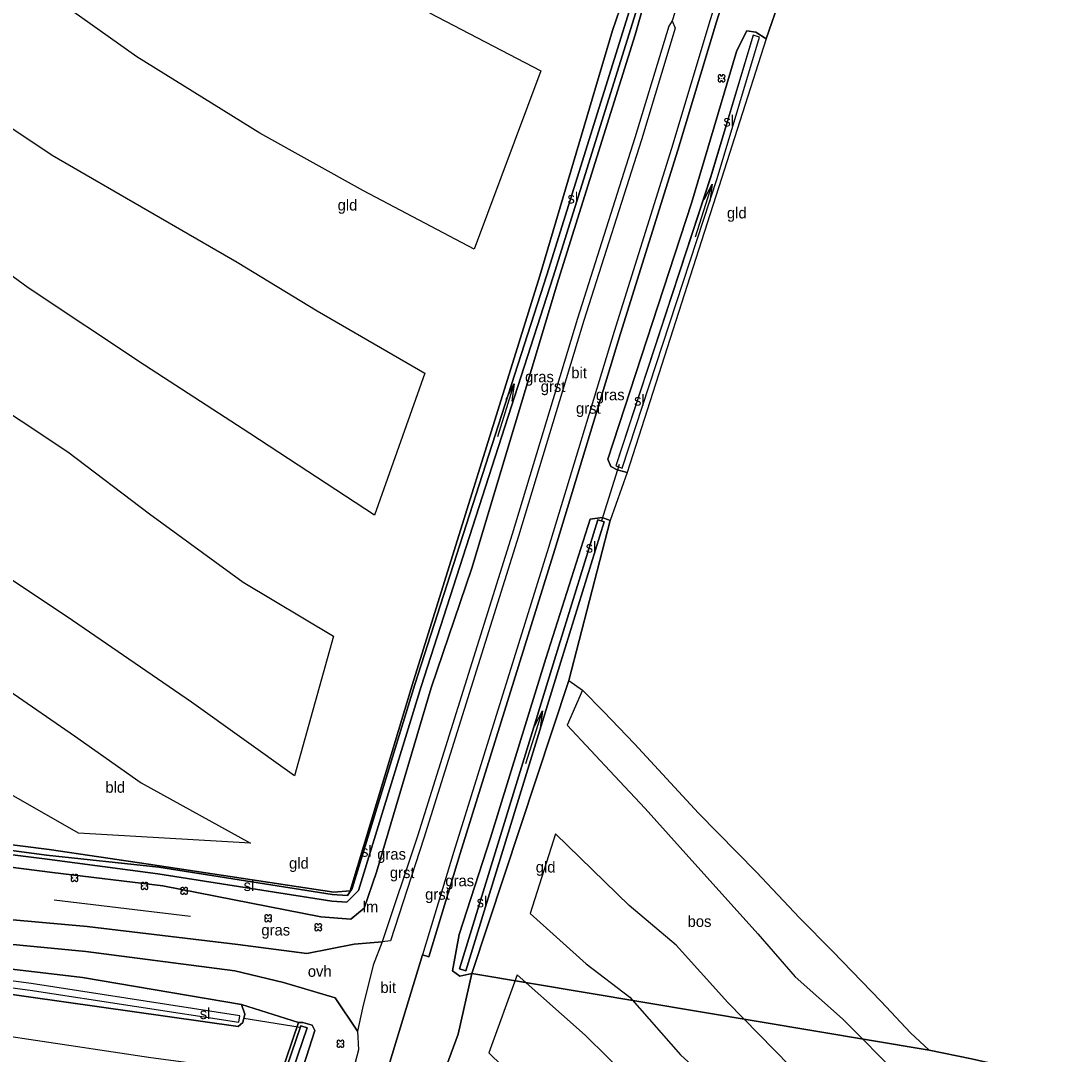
# Model space of a CAD drawing. Extents: x 154825 to 158680, y 370717 to 378075.
# Drawn here: x 155897.3 to 155990.5, y 376817.5 to 376911 of the extents above; entities that cross this region are included whole.
import ezdxf

# ---------------------------------------------------------------- set-up
doc = ezdxf.new("R2010")
doc.units = 0
for name, color, linetype in [('bitumenverharding(vs)', 7, 'Continuous'), ('boom', 7, 'Continuous'), ('bos(vs)', 7, 'Continuous'), ('bouwland_akkerland(vs)', 7, 'Continuous'), ('cultuurscheiding', 7, 'Continuous'), ('duiker lijn', 7, 'Continuous'), ('grasland_productiegrasl(vs)', 7, 'Continuous'), ('grazige vegetatie(vs)', 7, 'Continuous'), ('groensteenverh(vs)', 7, 'Continuous'), ('hoogteverschillijn', 7, 'Continuous'), ('insteek sloot', 7, 'Continuous'), ('maaiveldlijn algemeen', 7, 'Continuous'), ('maaiveldlijn algemeen - gesloten verharding', 7, 'Continuous'), ('maaiveldlijn algemeen - onverhard', 7, 'Continuous'), ('onverhard(vs)', 7, 'Continuous'), ('Sloot bodem', 7, 'Continuous'), ('sloot(vs)', 7, 'Continuous'), ('stroomrichting  watergangen', 7, 'Continuous'), ('verlichtingsobject', 7, 'Continuous'), ('vlak_akkerland', 7, 'Continuous'), ('vlak_Bos', 7, 'Continuous'), ('vlak_Grasland', 7, 'Continuous'), ('vlak_Grazige_vegetatie', 7, 'Continuous')]:
    doc.layers.add(name, color=color, linetype=linetype)

msp = doc.modelspace()

# ---------------------------------------------------------------- linework, layer by layer
at = {"layer": 'boom'}
for centre in [(155960.688, 376905.781), (155902.151, 376833.437), (155908.483, 376832.716), (155912.066, 376832.272), (155919.669, 376829.786), (155924.198, 376828.969), (155926.209, 376818.435)]:
    msp.add_circle(centre, 0.006, dxfattribs=at)
for centre, start, end in [((155960.529, 376905.939), 357.07502, 272.92498), ((155960.846, 376905.939), 267.07502, 182.92498), ((155960.529, 376905.623), 87.07502, 2.92498), ((155960.846, 376905.623), 177.07502, 92.92498), ((155901.993, 376833.595), 357.07502, 272.92498), ((155901.993, 376833.279), 87.07502, 2.92498), ((155902.309, 376833.595), 267.07502, 182.92498), ((155902.309, 376833.279), 177.07502, 92.92498), ((155908.325, 376832.874), 357.07502, 272.92498), ((155908.325, 376832.558), 87.07502, 2.92498), ((155908.641, 376832.874), 267.07502, 182.92498), ((155908.641, 376832.558), 177.07502, 92.92498), ((155911.908, 376832.43), 357.07502, 272.92498), ((155911.908, 376832.114), 87.07502, 2.92498), ((155912.224, 376832.43), 267.07502, 182.92498), ((155912.224, 376832.114), 177.07502, 92.92498), ((155919.511, 376829.945), 357.07502, 272.92498), ((155919.511, 376829.628), 87.07502, 2.92498), ((155919.827, 376829.945), 267.07502, 182.92498), ((155919.827, 376829.628), 177.07502, 92.92498), ((155924.04, 376829.127), 357.07502, 272.92498), ((155924.04, 376828.811), 87.07502, 2.92498), ((155924.356, 376829.127), 267.07502, 182.92498), ((155924.356, 376828.811), 177.07502, 92.92498), ((155926.051, 376818.593), 357.07502, 272.92498), ((155926.051, 376818.277), 87.07502, 2.92498), ((155926.367, 376818.593), 267.07502, 182.92498), ((155926.367, 376818.277), 177.07502, 92.92498)]:
    msp.add_arc(centre, 0.158, start, end, dxfattribs=at)
at = {"layer": 'cultuurscheiding'}
msp.add_lwpolyline([(155979.48, 376817.84), (155938.088, 376824.783)], dxfattribs=at)
at = {"layer": 'duiker lijn'}
for points in [[(155951.437, 376870.843), (155949.812, 376865.757)], [(155922.58, 376819.892), (155917.474, 376820.734)]]:
    msp.add_lwpolyline(points, dxfattribs=at)
at = {"layer": 'groensteenverh(vs)'}
for points in [[(155977.72, 376967.095), (155968.744, 376938.018), (155960.234, 376910.907), (155956.721, 376899.271), (155951.551, 376882.687), (155945.605, 376863.158), (155937.043, 376835.644), (155934.215, 376826.303), (155933.641, 376826.476)], [(155956.222, 376910.974), (155955.911, 376910.5), (155952.857, 376900.403), (155947.662, 376884.051), (155941.732, 376864.545), (155933.195, 376837.219), (155929.981, 376827.647)]]:
    msp.add_lwpolyline(points, dxfattribs=at)
at = {"layer": 'hoogteverschillijn'}
for points in [[(155874.66, 376916.61), (155883.38, 376909.98), (155892.9, 376903.67), (155900.14, 376898.84), (155908.78, 376893.81), (155916.88, 376889.16), (155924.11, 376884.74), (155933.83, 376879.1), (155929.3, 376866.27), (155918.02, 376873.64), (155908.49, 376879.84), (155897.95, 376886.83), (155887.87, 376894.23), (155879.15, 376901.66), (155869.11, 376909.47), (155861.42, 376914.58)], [(155934.27, 376911.71), (155944.34, 376906.47), (155938.31, 376890.31), (155928.29, 376895.61), (155918.93, 376900.81), (155907.78, 376907.73), (155899.49, 376913.63)], [(155893.08, 376877.6), (155901.55, 376871.98), (155908.94, 376866.37), (155917.4, 376860.19), (155925.57, 376855.3), (155922.04, 376842.67), (155912.73, 376849.34), (155901.98, 376856.72), (155891.51, 376863.7)], [(155896.2, 376850.4), (155902.14, 376846.3), (155908.19, 376842.04), (155918.07, 376836.57), (155902.52, 376837.48), (155889.68, 376844.82)], [(155991.54, 376815.37), (155987.15, 376816.19), (155983.3, 376817.06), (155979.48, 376817.84), (155977.78, 376819.42), (155975.13, 376822.26), (155970.74, 376826.8), (155967.74, 376829.82), (155963.85, 376833.97), (155958.6, 376839.3), (155952.8, 376845.56), (155950.02, 376848.51), (155948.11, 376850.44), (155946.71, 376847.26), (155951.01, 376842.68), (155953.78, 376839.71), (155956.93, 376836.2), (155963.97, 376828.38), (155967.35, 376824.5), (155971.64, 376820.68), (155976.86, 376815.44), (155982.97, 376813.8), (155989.69, 376811.89), (155993.57, 376808.55)], [(155994.4, 376800.74), (155989.65, 376805.26), (155985.81, 376808.54), (155979.65, 376810.44), (155973.59, 376812.11), (155966.88, 376816.43), (155961.26, 376822.16), (155956.57, 376827.35), (155952.32, 376830.93), (155945.66, 376837.42), (155943.37, 376830.22), (155948.43, 376825.65), (155952.39, 376822.65), (155956.98, 376817.44), (155961.53, 376813.27), (155966.61, 376809.39), (155973.68, 376806.3), (155978.62, 376805.16), (155983.98, 376802.87), (155990.83, 376797.67)], [(155993.54, 376788.54), (155987.44, 376794.17), (155981.92, 376798.48), (155974.82, 376800.89), (155968.62, 376803.98), (155960.44, 376808.18), (155954.42, 376813.24), (155948.36, 376819.22), (155942.2, 376824.67), (155939.62, 376817.62), (155945.74, 376811.67), (155952.61, 376806.55), (155957.57, 376802.23), (155965.26, 376798.55), (155971.4, 376796.09), (155977.96, 376793.86), (155983.98, 376791.3), (155988.91, 376785.9), (155994.12, 376780.51)], [(155892.77, 376819.62), (155901.63, 376818.3), (155909.05, 376817.18), (155915.86, 376816.29), (155914.76, 376811.73), (155909.61, 376812.55), (155902.04, 376813.96), (155906.06, 376808.23), (155913.64, 376806.73), (155912.58, 376801.38), (155907.51, 376802.62), (155910.8, 376795.72), (155909.95, 376790.82), (155907.52, 376783.18)]]:
    msp.add_lwpolyline(points, dxfattribs=at)
at = {"layer": 'insteek sloot'}
for points in [[(155951.484, 376912.036), (155950.814, 376910.099), (155944.237, 376887.926), (155932.687, 376850.872), (155927.096, 376832.283), (155925.603, 376832.138), (155908.833, 376834.685), (155899.864, 376836), (155880.293, 376838.495), (155852.575, 376842.402), (155830.686, 376845.172), (155807.489, 376848.441), (155806.694, 376849.699), (155808.966, 376866.305), (155812.214, 376885.553), (155815.215, 376903.439), (155820.866, 376929.025), (155827.55, 376949.898), (155825.681, 376950.598)], [(155804.241, 376845.729), (155806.902, 376846.291), (155830.147, 376843.55), (155852.379, 376840.447), (155880.092, 376836.472), (155886.442, 376835.669), (155900.165, 376833.933), (155910.133, 376832.737), (155924.429, 376829.917), (155927.161, 376829.707), (155928.346, 376830.7), (155929.483, 376833.947), (155934.432, 376850.627), (155938.102, 376861.472), (155945.947, 376887.569), (155952.862, 376909.704), (155953.448, 376911.726), (155952.686, 376912.04), (155951.484, 376912.036)], [(155964.725, 376909.365), (155960.678, 376896.712), (155952.16, 376870.127), (155951.234, 376870.353), (155950.663, 376870.658), (155950.388, 376871.33), (155957.961, 376894.501), (155962.069, 376908.29), (155962.974, 376910.09), (155963.786, 376909.951), (155964.725, 376909.365)], [(155938.088, 376824.783), (155946.877, 376851.31), (155950.606, 376865.784), (155949.894, 376866.057), (155948.794, 376865.907), (155944.794, 376853.29), (155939.772, 376837.056), (155936.957, 376828.326), (155936.339, 376825.028), (155937.012, 376824.556), (155938.088, 376824.783)], [(155917.26, 376821.973), (155902.886, 376824.441), (155881.115, 376826.991), (155860.068, 376829.768), (155840.335, 376832.598), (155818.194, 376835.658), (155799.768, 376838.374), (155777.887, 376841.551)], [(155917.26, 376821.973), (155917.56, 376821.097), (155917.383, 376820.353), (155916.958, 376819.986), (155897.988, 376822.688), (155867.209, 376827.039), (155832.392, 376831.871), (155801.868, 376835.981), (155784.259, 376838.54)], [(155922.41, 376820.35), (155922.793, 376820.353), (155923.641, 376820.13), (155923.9, 376819.644), (155920.317, 376808.448), (155919.501, 376808.407), (155918.792, 376808.654), (155918.527, 376808.892)], [(155918.527, 376808.892), (155922.41, 376820.35)]]:
    msp.add_lwpolyline(points, dxfattribs=at)
at = {"layer": 'maaiveldlijn algemeen'}
for points in [[(155964.725, 376909.365), (155966.025, 376913.137)], [(155912.643, 376829.939), (155900.303, 376831.417)], [(155938.088, 376824.783), (155936.865, 376819.298), (155934.67, 376813.332), (155933.83, 376809.418)], [(155917.26, 376821.973), (155922.41, 376820.35)]]:
    msp.add_lwpolyline(points, dxfattribs=at)
at = {"layer": 'maaiveldlijn algemeen - gesloten verharding'}
for points in [[(155985.483, 376994.159), (155980.924, 376979.243), (155977.148, 376967.275), (155968.171, 376938.195), (155959.659, 376911.08), (155956.146, 376899.444), (155950.978, 376882.866), (155945.031, 376863.333), (155936.469, 376835.818), (155933.641, 376826.476)], [(155958.139, 376917.306), (155956.695, 376912.479), (155956.222, 376910.974)], [(155956.222, 376910.974), (155956.485, 376910.326), (155953.431, 376900.229), (155948.234, 376883.869), (155942.306, 376864.371), (155933.765, 376837.032), (155930.729, 376827.738), (155929.981, 376827.647)], [(155929.981, 376827.647), (155929.172, 376825.559), (155928.198, 376821.661), (155927.76, 376819.579)], [(155933.641, 376826.476), (155930.262, 376815.394), (155928.376, 376809.621), (155923.203, 376793.574), (155918.573, 376779.226), (155918.797, 376778.825), (155918.219, 376777.336)], [(155927.76, 376819.579), (155927.858, 376817.889), (155927.55, 376816.743), (155925.323, 376810.209), (155920.199, 376794.655), (155915.514, 376780.124), (155915.103, 376779.586), (155914.606, 376778.187)]]:
    msp.add_lwpolyline(points, dxfattribs=at)
at = {"layer": 'maaiveldlijn algemeen - onverhard'}
for points in [[(155761.967, 376849.002), (155778.08, 376846.245), (155800.284, 376842.691), (155818.669, 376839.483), (155840.897, 376835.856), (155860.131, 376833.497), (155881.395, 376830.99), (155903.307, 376829.04), (155916.926, 376827.416), (155923.183, 376826.586), (155927.443, 376827.436), (155929.981, 376827.647)], [(155927.76, 376819.579), (155925.738, 376822.586), (155921.049, 376823.976), (155916.669, 376825.037), (155903.184, 376826.77), (155881.477, 376828.865), (155859.801, 376831.069), (155840.386, 376833.739), (155818.229, 376837.165), (155799.731, 376840.225), (155778.256, 376843.757), (155761.03, 376845.988)]]:
    msp.add_lwpolyline(points, dxfattribs=at)
at = {"layer": 'Sloot bodem'}
for points in [[(155952.923, 376911.734), (155945.447, 376887.824), (155933.513, 376850.767), (155927.843, 376832.294), (155926.8, 376831.247), (155925.433, 376831.343), (155909.701, 376833.806), (155899.669, 376835.148), (155880.198, 376837.58), (155852.258, 376841.398), (155830.404, 376844.191), (155805.778, 376847.032), (155807.507, 376865.982), (155810.821, 376885.921), (155813.803, 376903.842), (155819.136, 376929.121)], [(155820.25, 376929.183), (155814.745, 376903.443), (155811.718, 376885.721), (155808.507, 376866.3), (155806.195, 376848.203), (155830.558, 376844.761), (155852.388, 376841.941), (155880.241, 376838.084), (155899.625, 376835.502), (155909.794, 376834.399), (155925.475, 376831.942), (155926.842, 376831.846), (155927.269, 376832.47), (155932.942, 376850.95), (155944.874, 376888.003), (155952.35, 376911.913)], [(155960.278, 376896.707), (155964.135, 376909.508), (155963.561, 376909.681), (155959.704, 376896.88), (155951.136, 376870.707), (155951.707, 376870.52), (155960.278, 376896.707)], [(155946.133, 376852.983), (155937.55, 376825.034), (155936.976, 376825.21), (155945.56, 376853.159), (155949.508, 376865.832), (155950.081, 376865.654), (155946.133, 376852.983)], [(155784.161, 376839.02), (155802.215, 376836.494), (155832.36, 376832.215), (155867.474, 376827.34), (155898.146, 376823.293), (155917.005, 376820.377), (155917.097, 376820.97), (155898.225, 376823.888), (155867.556, 376827.934), (155832.444, 376832.809), (155802.298, 376837.088), (155784.239, 376839.615)], [(155923.208, 376819.869), (155919.365, 376808.649), (155918.798, 376808.844), (155922.641, 376820.064), (155923.208, 376819.869)]]:
    msp.add_lwpolyline(points, dxfattribs=at)
at = {"layer": 'stroomrichting  watergangen'}
for p, q in [((155958.341, 376891.427), (155959.825, 376896.194)), ((155959.807, 376896.184), (155959.083, 376894.78)), ((155959.825, 376896.194), (155959.625, 376894.628)), ((155940.441, 376873.379), (155941.925, 376878.146)), ((155941.908, 376878.136), (155941.184, 376876.733)), ((155941.925, 376878.146), (155941.725, 376876.58)), ((155942.995, 376843.781), (155944.479, 376848.548)), ((155944.461, 376848.538), (155943.738, 376847.135)), ((155944.479, 376848.548), (155944.279, 376846.982))]:
    msp.add_line(p, q, dxfattribs=at)
at = {"layer": 'vlak_akkerland'}
msp.add_lwpolyline([(155951.484, 376912.036), (155950.814, 376910.099), (155944.237, 376887.926), (155932.687, 376850.872), (155927.096, 376832.283), (155925.603, 376832.138), (155908.833, 376834.685), (155899.864, 376836), (155880.293, 376838.495), (155852.575, 376842.402), (155830.686, 376845.172), (155807.489, 376848.441), (155806.694, 376849.699), (155808.966, 376866.305), (155812.214, 376885.553), (155815.215, 376903.439), (155820.866, 376929.025)], dxfattribs=at)
at = {"layer": 'vlak_Bos'}
msp.add_lwpolyline([(155977.78, 376819.42), (155979.48, 376817.84), (155938.088, 376824.783), (155946.877, 376851.31), (155948.11, 376850.44), (155950.02, 376848.51), (155952.8, 376845.56), (155958.6, 376839.3), (155963.85, 376833.97), (155967.74, 376829.82), (155970.74, 376826.8), (155975.13, 376822.26)], close=True, dxfattribs=at)
at = {"layer": 'vlak_Grasland'}
for points in [[(155867.209, 376827.039), (155897.988, 376822.688), (155916.958, 376819.986), (155917.383, 376820.353), (155917.56, 376821.097), (155917.26, 376821.973), (155922.41, 376820.35), (155918.527, 376808.892)], [(155994.63, 376752.99), (155989.75, 376757.57), (155983.86, 376763.3), (155977.04, 376769.92), (155970.97, 376775.93), (155964.55, 376782.41), (155961.15, 376785.81), (155957.13, 376789.87), (155953.65, 376793.47), (155950.05, 376797.13), (155946.32, 376800.8), (155945.72, 376801.27), (155939.49, 376801.04), (155932.16, 376801.12), (155929.6, 376794.385), (155933.255, 376806.372), (155933.83, 376809.418), (155934.67, 376813.332), (155936.865, 376819.298), (155938.088, 376824.783), (155979.48, 376817.84), (155983.3, 376817.06), (155987.15, 376816.19), (155991.54, 376815.37)]]:
    msp.add_lwpolyline(points, dxfattribs=at)
at = {"layer": 'vlak_Grazige_vegetatie'}
for points in [[(155930.262, 376815.394), (155933.641, 376826.476), (155934.215, 376826.303), (155937.043, 376835.644), (155945.605, 376863.158), (155951.551, 376882.687), (155956.721, 376899.271), (155960.234, 376910.907), (155968.744, 376938.018)], [(155819.136, 376929.121), (155813.803, 376903.842), (155810.821, 376885.921), (155807.507, 376865.982), (155805.777, 376847.032), (155830.404, 376844.191), (155852.258, 376841.398), (155880.198, 376837.58), (155899.669, 376835.148), (155909.701, 376833.806), (155925.433, 376831.343), (155926.8, 376831.247), (155927.843, 376832.294), (155933.513, 376850.766), (155945.447, 376887.823), (155952.923, 376911.734)], [(155952.35, 376911.913), (155944.874, 376888.003), (155932.942, 376850.951), (155927.269, 376832.47), (155926.842, 376831.846), (155925.475, 376831.942), (155909.794, 376834.399), (155899.625, 376835.503), (155880.241, 376838.084), (155852.388, 376841.941), (155830.558, 376844.761), (155806.196, 376848.203), (155808.507, 376866.3), (155811.718, 376885.721), (155814.745, 376903.443), (155820.25, 376929.183)], [(155820.866, 376929.025), (155815.215, 376903.439), (155812.214, 376885.553), (155808.966, 376866.305), (155806.694, 376849.699), (155807.489, 376848.441), (155830.686, 376845.172), (155852.575, 376842.402), (155880.293, 376838.495), (155899.864, 376836), (155908.833, 376834.685), (155925.603, 376832.138), (155927.096, 376832.283), (155932.687, 376850.872), (155944.237, 376887.926), (155950.814, 376910.099), (155951.484, 376912.036)], [(155953.448, 376911.727), (155952.862, 376909.704), (155945.947, 376887.569), (155938.102, 376861.473), (155934.431, 376850.627), (155929.483, 376833.947), (155928.346, 376830.701), (155927.161, 376829.707), (155924.429, 376829.917), (155910.133, 376832.737), (155900.165, 376833.933), (155886.442, 376835.669), (155880.092, 376836.472), (155852.379, 376840.447), (155830.147, 376843.55), (155806.902, 376846.291), (155804.241, 376845.729), (155807.718, 376874.509), (155811.737, 376900.951), (155817.696, 376927.172)], [(155966.025, 376913.137), (155964.725, 376909.365), (155963.786, 376909.951), (155962.974, 376910.09), (155962.069, 376908.29), (155957.96, 376894.501), (155950.388, 376871.33), (155950.663, 376870.658), (155951.234, 376870.352), (155952.16, 376870.127), (155950.606, 376865.784), (155949.894, 376866.057), (155948.794, 376865.907), (155944.794, 376853.29), (155939.772, 376837.056), (155936.957, 376828.326), (155936.339, 376825.028), (155937.012, 376824.556), (155938.088, 376824.783), (155936.865, 376819.298), (155934.67, 376813.332)], [(155762.486, 376851.795), (155803.105, 376845.017), (155809.069, 376842.912), (155820.668, 376840.76), (155835.504, 376838.712), (155854.844, 376836.168), (155869.255, 376833.193), (155871.295, 376833.071), (155885.394, 376831.911), (155886.442, 376835.669), (155900.165, 376833.933), (155910.133, 376832.737), (155924.429, 376829.917), (155927.161, 376829.707), (155928.346, 376830.701), (155929.483, 376833.947), (155934.431, 376850.627), (155938.102, 376861.473), (155945.947, 376887.569), (155952.862, 376909.704), (155953.448, 376911.727)], [(155956.695, 376912.479), (155956.222, 376910.974), (155955.911, 376910.5), (155952.857, 376900.403), (155947.662, 376884.051), (155941.732, 376864.545), (155933.195, 376837.219), (155929.981, 376827.647), (155927.443, 376827.436), (155923.183, 376826.586), (155916.926, 376827.416), (155903.307, 376829.04), (155881.395, 376830.99), (155860.131, 376833.497), (155840.897, 376835.856), (155818.669, 376839.483), (155800.284, 376842.69), (155778.08, 376846.245)], [(155777.887, 376841.551), (155799.768, 376838.374), (155818.194, 376835.658), (155840.335, 376832.598), (155860.068, 376829.768), (155881.115, 376826.991), (155902.886, 376824.442), (155917.26, 376821.973), (155917.56, 376821.097), (155917.383, 376820.353), (155916.958, 376819.986), (155897.988, 376822.688), (155867.209, 376827.039), (155832.392, 376831.872), (155801.868, 376835.981), (155784.259, 376838.54)], [(155784.161, 376839.02), (155802.215, 376836.494), (155832.36, 376832.215), (155867.474, 376827.34), (155898.146, 376823.293), (155917.005, 376820.377), (155917.097, 376820.97), (155898.225, 376823.888), (155867.556, 376827.934), (155832.444, 376832.809), (155802.298, 376837.088), (155784.239, 376839.615)], [(155881.477, 376828.865), (155903.184, 376826.77), (155916.669, 376825.037), (155921.049, 376823.977), (155925.738, 376822.586), (155927.76, 376819.579), (155927.858, 376817.889), (155927.55, 376816.743)], [(155920.317, 376808.448), (155923.9, 376819.644), (155923.641, 376820.13), (155922.793, 376820.353), (155922.41, 376820.35), (155917.26, 376821.973), (155902.886, 376824.442), (155881.115, 376826.991)]]:
    msp.add_lwpolyline(points, dxfattribs=at)
for points in [[(155963.786, 376909.951), (155964.725, 376909.365), (155960.678, 376896.712), (155952.16, 376870.127), (155951.234, 376870.352), (155950.663, 376870.658), (155950.388, 376871.33), (155957.96, 376894.501), (155962.069, 376908.29), (155962.974, 376910.09)], [(155951.136, 376870.707), (155951.707, 376870.52), (155960.278, 376896.707), (155964.135, 376909.508), (155963.561, 376909.681), (155959.703, 376896.88)], [(155949.894, 376866.057), (155950.606, 376865.784), (155946.877, 376851.31), (155938.088, 376824.783), (155937.012, 376824.556), (155936.339, 376825.028), (155936.957, 376828.326), (155939.772, 376837.056), (155944.794, 376853.29), (155948.794, 376865.907)], [(155936.976, 376825.21), (155937.55, 376825.034), (155946.133, 376852.983), (155950.081, 376865.654), (155949.508, 376865.832), (155945.56, 376853.159)], [(155923.641, 376820.13), (155923.9, 376819.644), (155920.317, 376808.448), (155919.501, 376808.407), (155918.792, 376808.654), (155918.527, 376808.892), (155922.41, 376820.35), (155922.793, 376820.353)], [(155918.798, 376808.843), (155919.365, 376808.649), (155923.208, 376819.869), (155922.641, 376820.064)]]:
    msp.add_lwpolyline(points, close=True, dxfattribs=at)

# ---------------------------------------------------------------- texts
at = {"layer": 'bitumenverharding(vs)'}
for p in [(155947.095, 376878.646), (155929.828, 376823.034)]:
    msp.add_text('bit', height=1, dxfattribs=at).set_placement(p)
at = {"layer": 'bos(vs)'}
msp.add_text('bos', height=1, dxfattribs=at).set_placement((155957.616, 376829.008))
at = {"layer": 'bouwland_akkerland(vs)'}
msp.add_text('bld', height=1, dxfattribs=at).set_placement((155904.944, 376841.143))
at = {"layer": 'grasland_productiegrasl(vs)'}
for p in [(155925.955, 376893.823), (155961.174, 376893.104), (155921.559, 376834.276), (155943.88, 376833.925)]:
    msp.add_text('gld', height=1, dxfattribs=at).set_placement(p)
at = {"layer": 'grazige vegetatie(vs)'}
for p in [(155942.915, 376878.275), (155949.319, 376876.654), (155929.538, 376835.093), (155935.7, 376832.688), (155919.054, 376828.23)]:
    msp.add_text('gras', height=1, dxfattribs=at).set_placement(p)
at = {"layer": 'groensteenverh(vs)'}
for p in [(155944.33, 376877.41), (155947.518, 376875.437), (155930.683, 376833.424), (155933.872, 376831.465)]:
    msp.add_text('grst', height=1, dxfattribs=at).set_placement(p)
at = {"layer": 'onverhard(vs)'}
msp.add_text('ovh', height=1, dxfattribs=at).set_placement((155923.258, 376824.493))
at = {"layer": 'sloot(vs)'}
for p in [(155960.852, 376901.426), (155946.747, 376894.461), (155952.773, 376876.173), (155948.395, 376862.865), (155928.074, 376835.349), (155917.454, 376832.255), (155938.532, 376830.776), (155913.482, 376820.662)]:
    msp.add_text('sl', height=1, dxfattribs=at).set_placement(p)
at = {"layer": 'verlichtingsobject'}
msp.add_text('lm', height=1, dxfattribs=at).set_placement((155928.22, 376830.331))

doc.saveas('drawing.dxf')
